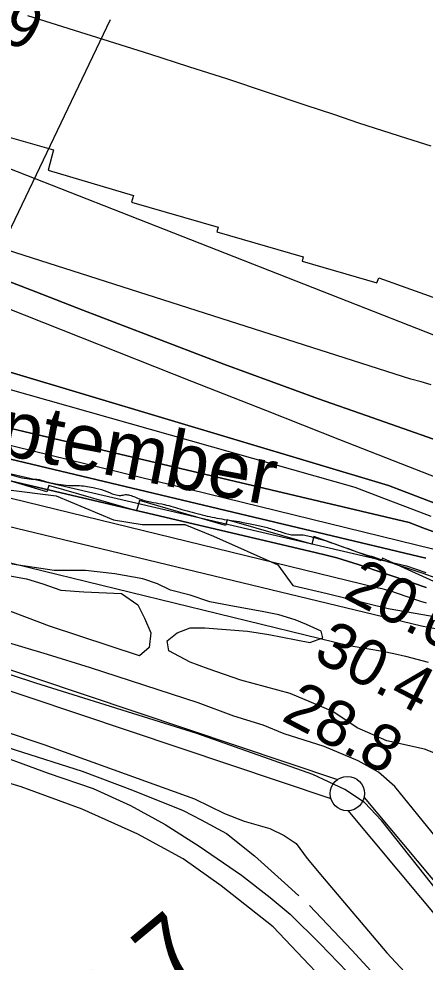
# Model space of a CAD drawing. Extents: x 3297772 to 3335630, y 634068 to 659439.
# Drawn here: x 3319783 to 3320374, y 645551 to 646925 of the extents above; entities that cross this region are included whole.
import ezdxf

# ---------------------------------------------------------------- set-up
doc = ezdxf.new("R2010")
doc.units = 0
for name, color, linetype in [('V-FLOD-BASE', 7, 'Continuous'), ('V-LEVE-TOET', 7, 'Continuous'), ('V-RIVR-EDGE', 7, 'Continuous'), ('V-RIVR-IDEN', 7, 'Continuous'), ('V-RIVR-RANG', 7, 'Continuous'), ('V-ROAD-CNTR', 7, 'Continuous'), ('V-RRAP-RVMT', 7, 'Continuous'), ('V-SITE-VEGE', 7, 'Continuous'), ('V-SURV-IDEN', 7, 'Continuous'), ('V-SURV-LINE', 7, 'Continuous'), ('V-TOPO-DPTH', 7, 'Continuous'), ('V-TOPO-MAJR', 7, 'Continuous'), ('V-TOPO-MINR', 7, 'Continuous'), ('V-TOPO-SHOR', 7, 'Continuous'), ('V-TOPO-WATR', 7, 'Continuous')]:
    doc.layers.add(name, color=color, linetype=linetype)

msp = doc.modelspace()

# ---------------------------------------------------------------- linework, layer by layer
at = {"layer": 'V-FLOD-BASE'}
msp.add_lwpolyline([(3320403.7, 645639.9), (3320311.2, 645756.9), (3320285.7, 645783.6), (3320257.2, 645802.4), (3320210.4, 645824.2), (3320041.7, 645883.8), (3319807.3, 645957.2), (3319603.1, 646024.5), (3319388.4, 646097.2), (3319091.5, 646194.7), (3318836.5, 646282.1)], dxfattribs=at)
at = {"layer": 'V-LEVE-TOET'}
for points in [[(3320390.6, 645731.9), (3320330, 645806.6), (3320306.1, 645827.7), (3320276.8, 645844.1), (3320226.9, 645865.1), (3320169.1, 645883.6), (3320138.2, 645896.1), (3320095.4, 645909.2), (3320043.9, 645928.6), (3319887.2, 645979.6), (3319824.6, 645998.9), (3319721.7, 646029.8), (3319592.6, 646079.4), (3319460.4, 646121.2), (3319353.4, 646159.9), (3319234.7, 646194.6), (3319013.7, 646271.3), (3318918.7, 646303.8)], [(3318948.8, 646161.3), (3319040.6, 646128), (3319139.6, 646094.7), (3319302.7, 646039.8), (3319440.5, 645992.5), (3319640.9, 645927.6), (3319819, 645868), (3320038.4, 645789), (3320082, 645767.2), (3320110.5, 645756.3), (3320147.8, 645745.5), (3320169.1, 645735.4), (3320186.6, 645723.7), (3320202.6, 645701.7), (3320224.9, 645675), (3320318.1, 645564.2), (3320410.4, 645465.3), (3320451, 645424.5), (3320501.1, 645383)]]:
    msp.add_lwpolyline(points, dxfattribs=at)
at = {"layer": 'V-RIVR-EDGE'}
msp.add_spline([(3314762, 649274.1), (3314790.4, 649247.4), (3314813.8, 649224.7), (3314842.2, 649196.8), (3314862.2, 649176.3), (3314886.7, 649152.1), (3314900.2, 649138.2), (3314917.7, 649122.8), (3314932.6, 649107.7), (3314956.3, 649080.3), (3314980, 649058.3), (3315004.5, 649036.7), (3315016.5, 649023.5), (3315034, 649001.5), (3315053.7, 648981.3), (3315075.9, 648956.4), (3315089, 648943.6), (3315090.5, 648939.2), (3315095.2, 648931.5), (3315116, 648911.7), (3315165.6, 648868.8), (3315188.6, 648851.6), (3315212.7, 648837.3), (3315236.1, 648818.9), (3315259, 648798.8), (3315272.2, 648788.2), (3315289, 648777.9), (3315298.5, 648775.3), (3315308.3, 648771.2), (3315320.4, 648764.6), (3315332, 648756.2), (3315345.5, 648749.2), (3315366, 648738.6), (3315396.3, 648721.7), (3315420, 648711), (3315449.6, 648697.4), (3315476.3, 648687.1), (3315490.9, 648684.9), (3315496.7, 648684.1), (3315504, 648679.4), (3315514.6, 648672), (3315516.8, 648666.9), (3315520.8, 648653.4), (3315527, 648639.8), (3315536.8, 648627), (3315543, 648621.5), (3315546.6, 648621.1), (3315552.5, 648618.6), (3315560.1, 648612.7), (3315568.5, 648604.6), (3315578, 648595.8), (3315593, 648584.8), (3315611.6, 648575.7), (3315624.4, 648570.1), (3315635, 648566.8), (3315640.8, 648563.5), (3315648.5, 648562.4), (3315656.2, 648563.1), (3315662.4, 648563.8), (3315671.1, 648560.9), (3315676.3, 648556.1), (3315679.2, 648552.8), (3315684.3, 648552.1), (3315687.9, 648551), (3315695.9, 648534.9), (3315725.4, 648474.9), (3315731.9, 648461.3), (3315736.7, 648455.8), (3315746.5, 648446.7), (3315756.7, 648438.2), (3315765.5, 648425.8), (3315772.8, 648408.9), (3315789.5, 648388.1), (3315803.7, 648364.6), (3315814.3, 648346.7), (3315830, 648328.4), (3315850.7, 648307.5), (3315869.7, 648285.5), (3315901.8, 648253.6), (3315937.5, 648219.5), (3315960.5, 648195.4), (3315980.9, 648175.6), (3315989.3, 648173.4), (3316000.6, 648165.3), (3316008.7, 648158.3), (3316031.6, 648140.7), (3316054.6, 648124.2), (3316085.3, 648105.5), (3316118.5, 648083.1), (3316140, 648068.8), (3316157.2, 648061.8), (3316170.3, 648056.7), (3316187.1, 648044.9), (3316195.5, 648041.2), (3316205.4, 648037.9), (3316215.2, 648033.2), (3316238.6, 648020.7), (3316243.7, 648016.6), (3316255, 648007.5), (3316268.9, 648000.1), (3316287.9, 647988.4), (3316303.6, 647982.9), (3316316.7, 647978.4), (3316339.4, 647970), (3316356.2, 647962.3), (3316375.5, 647951.2), (3316396.3, 647938), (3316428.4, 647920.4), (3316474.1, 647891.4), (3316489.4, 647882.2), (3316507.7, 647873.4), (3316517.5, 647867.9), (3316538, 647856.9), (3316563.5, 647842.9), (3316578.8, 647832.3), (3316609.5, 647815), (3316632.9, 647802.2), (3316646.7, 647790.8), (3316669.3, 647772.5), (3316682.1, 647762.2), (3316696.3, 647755.2), (3316758.8, 647713.8), (3316797.8, 647691), (3316819.7, 647676.7), (3316836.9, 647665.7), (3316865, 647650.6), (3316895.6, 647634.1), (3316912.4, 647623.1), (3316940.9, 647606.6), (3316996.7, 647574.7), (3317044.6, 647546.8), (3317079.2, 647525.1), (3317111.4, 647506.4), (3317148.2, 647484.7), (3317188.4, 647460.9), (3317213.9, 647442.2), (3317231.4, 647430.4), (3317255.2, 647416.8), (3317274.1, 647402.2), (3317293.1, 647391.1), (3317310.3, 647384.5), (3317333.7, 647373.5), (3317372.7, 647350.4), (3317404.1, 647330.9), (3317491, 647282.8), (3317527.8, 647261.5), (3317547.2, 647249.8), (3317572.4, 647235.8), (3317600.9, 647222.6), (3317629, 647207.9), (3317656.7, 647189.9), (3317738.1, 647140.4), (3317755.3, 647133.4), (3317770.2, 647129.3), (3317784.9, 647122.7), (3317817, 647104.7), (3317840.7, 647094.8), (3317860.1, 647086.3), (3317887.4, 647070.9), (3317915.2, 647055.5), (3317952.1, 647039.7), (3317972.9, 647031.6), (3318008.3, 647014.3), (3318036.8, 647000.4), (3318074.4, 646981.6), (3318112.3, 646961.1), (3318142.6, 646943.4), (3318179.2, 646929.1), (3318205.1, 646919.9), (3318226.3, 646909.6), (3318257.7, 646892.3), (3318275.6, 646883.5), (3318288.3, 646879.5), (3318295.7, 646878.7), (3318317.2, 646868.8), (3318334.3, 646857.1), (3318347.8, 646845.7), (3318357.3, 646839.5), (3318416.5, 646806.4), (3318459.2, 646781.4), (3318477.1, 646771.9), (3318503, 646757.2), (3318530, 646743.3), (3318562.1, 646728.6), (3318605.9, 646708.7), (3318643.9, 646694.4), (3318672.8, 646684.1), (3318690, 646679.6), (3318709, 646676.3), (3318727.2, 646668.6), (3318755, 646656.8), (3318823.6, 646624.5), (3318845.9, 646613.1), (3318855.7, 646607.9), (3318871.1, 646596.6), (3318891.9, 646586.3), (3318910.5, 646578.6), (3318938.6, 646566.8), (3318967.1, 646557.6), (3318997.8, 646547.6), (3319022.3, 646539.2), (3319054.4, 646528.1), (3319074.8, 646519.7), (3319089.5, 646516.3), (3319112.5, 646508.2), (3319131.8, 646500.1), (3319166.9, 646486.5), (3319188.4, 646478.8), (3319196.5, 646478.4), (3319208.5, 646474.7), (3319216.2, 646471.4), (3319227.9, 646467), (3319244, 646462.2), (3319256.7, 646456.3), (3319262.2, 646449.7), (3319272.4, 646444.6), (3319289.2, 646438.3), (3319307.1, 646430.3), (3319322.1, 646420.7), (3319337.4, 646409), (3319358.2, 646395), (3319379, 646382.6), (3319389.6, 646380), (3319400.6, 646376.3), (3319407.5, 646370.4), (3319419.9, 646362.7), (3319436.3, 646355), (3319463.4, 646344), (3319503.5, 646327.8), (3319544.4, 646316.7), (3319579.5, 646307.1), (3319606.2, 646299.4), (3319635, 646290.9), (3319681.4, 646280.9), (3319730.8, 646269.5), (3319772.8, 646260.6), (3319801.3, 646254.7), (3319808.9, 646254.6), (3319821.7, 646251.3), (3319836.3, 646248), (3319851, 646245.8), (3319868.1, 646245.4), (3319890.8, 646242.4), (3319906.9, 646238), (3319922.2, 646232.1), (3319931, 646230.9), (3319937.9, 646232), (3319943.8, 646231.3), (3319960.6, 646225), (3319978.8, 646220.6), (3319994.5, 646217.6), (3320020.1, 646210.6), (3320049.7, 646202.5), (3320078.2, 646196.6), (3320106.7, 646192.1), (3320126.8, 646188.1), (3320144.3, 646184), (3320163, 646178.1), (3320179.8, 646173.7), (3320196.6, 646173.3), (3320205.4, 646171.4), (3320223.3, 646166.6), (3320274.8, 646148.9), (3320298.9, 646141.2), (3320341.6, 646127.2), (3320376.3, 646115.8), (3320397.5, 646108.1), (3320422.7, 646098.5), (3320445, 646088.6), (3320487.3, 646068.4), (3320514, 646053.7), (3320559.9, 646025.8), (3320596.1, 646001.2), (3320629.6, 645979.6), (3320649.7, 645963.8), (3320673.1, 645949.8), (3320682.9, 645941.8), (3320711, 645921.2)], degree=3, dxfattribs=at)
at = {"layer": 'V-RIVR-RANG'}
msp.add_line((3319501, 646055.2), (3319915.9, 646924.2), dxfattribs=at)
at = {"layer": 'V-ROAD-CNTR'}
msp.add_lwpolyline([(3318578.7, 646244.3), (3319054.6, 646087.2), (3319608, 645901.5), (3319727.4, 645862), (3319825.5, 645826.2), (3319890.7, 645803.9), (3319945.4, 645779), (3319995.6, 645751.5), (3320045.1, 645719.9), (3320106.8, 645677.4), (3320148.4, 645645.1), (3320177.6, 645620.6), (3320221.5, 645577.6), (3320273.5, 645523.2), (3320384.6, 645404.9)], dxfattribs=at)
at = {"layer": 'V-RRAP-RVMT'}
for p, q in [((3319700.6, 646772.5), (3319833.3, 646734.3)), ((3319833.3, 646734.3), (3319825.3, 646704.6)), ((3319825.3, 646704.6), (3319949.6, 646668)), ((3319949.6, 646668), (3319946.8, 646658.4)), ((3319946.8, 646658.4), (3320072.7, 646621.8)), ((3320072.7, 646621.8), (3320071.1, 646615.1)), ((3320071.1, 646615.1), (3320196.6, 646578.4)), ((3320196.6, 646578.4), (3320195, 646572.2)), ((3320195, 646572.2), (3320303.8, 646540.6)), ((3320303.8, 646540.6), (3320306.6, 646548.1)), ((3320306.6, 646548.1), (3320425.4, 646505)), ((3319823.6, 646236.1), (3319702, 646272)), ((3319826.3, 646245.4), (3319823.6, 646236.1)), ((3319954.1, 646208.3), (3319826.3, 646245.4)), ((3319958.5, 646223.4), (3319954.1, 646208.3)), ((3320083.6, 646186.9), (3319958.5, 646223.4)), ((3320086, 646195.4), (3320083.6, 646186.9)), ((3320209, 646159.8), (3320086, 646195.4)), ((3320212.3, 646170.9), (3320209, 646159.8)), ((3320310.3, 646135.4), (3320212.3, 646170.9)), ((3320311.8, 646139.4), (3320310.3, 646135.4)), ((3320397.4, 646100.8), (3320311.8, 646139.4))]:
    msp.add_line(p, q, dxfattribs=at)
at = {"layer": 'V-SITE-VEGE'}
for points in [[(3318745.1, 646603.2), (3319169.8, 646459.4), (3319283.5, 646425.9), (3319340.4, 646397.5), (3319377.1, 646379.1), (3319410.6, 646344), (3319457.4, 646308.8), (3319489.2, 646287.1), (3319504.4, 646283.8), (3319589.5, 646265.3), (3319689.8, 646248.6), (3319837, 646230.2), (3319920.6, 646195.1), (3319962.4, 646188.4), (3320024.3, 646188.4), (3320066.1, 646171.7), (3320159.7, 646129.9), (3320181.4, 646099.7), (3320231.6, 646088), (3320320.2, 646066.3), (3320407.2, 646051.2)], [(3319753.2, 646116.6), (3319793.7, 646109.4), (3319817.6, 646102.3), (3319843.8, 646092.7), (3319877.2, 646090.4), (3319932, 646088), (3319955.8, 646071.3), (3319965.4, 646052.2), (3319974.9, 646030.7), (3319972.5, 646009.3), (3319958.2, 645997.3), (3319827.1, 646040.3), (3319543.4, 646147.6)], [(3320408.8, 645847.1), (3320373, 645861.4), (3320318.2, 645873.3), (3320275.3, 645892.4), (3320239.5, 645916.2), (3320177.6, 645942.5), (3320106, 645961.6), (3320058.4, 645978.2), (3320032.1, 645987.8), (3320001.1, 646004.5), (3319998.8, 646018.8), (3320013.1, 646030.7), (3320032.1, 646037.9), (3320053.6, 646037.9), (3320084.6, 646035.5), (3320115.6, 646033.1), (3320146.6, 646028.3), (3320206.2, 646016.4), (3320225.2, 646023.6), (3320222.9, 646033.1), (3320201.4, 646042.6), (3320184.7, 646049.8), (3320160.9, 646057), (3320137, 646061.7), (3320096.5, 646068.9), (3320060.7, 646076), (3320032.1, 646085.6), (3320003.5, 646092.7), (3319984.5, 646102.3), (3319963, 646109.4), (3319922.5, 646116.6), (3319879.6, 646121.4), (3319834.3, 646121.4), (3319772.3, 646130.9)]]:
    msp.add_lwpolyline(points, dxfattribs=at)
at = {"layer": 'V-SURV-LINE'}
for points in [[(3318337.4, 646458.2), (3320246.7, 645817.1)], [(3320237.2, 645788.7), (3318327.9, 646429.7)], [(3320285.2, 645790.8), (3320496.8, 645537.7)], [(3320473.8, 645518.4), (3320262.2, 645771.6)]]:
    msp.add_lwpolyline(points, dxfattribs=at)
msp.add_circle((3320260.9, 645796.5), 25, dxfattribs=at)
at = {"layer": 'V-TOPO-DPTH'}
for points in [[(3318953.3, 646768.9), (3318982.8, 646757.8), (3319084.4, 646720.7), (3319544.5, 646588.3), (3319550.2, 646586.8), (3319555.9, 646585.2), (3319558.5, 646584.4), (3319562.9, 646583.1), (3319567.3, 646581.7), (3319571.6, 646580.3), (3319576, 646578.7), (3319581.3, 646576.8), (3319584.6, 646575.6), (3319587.9, 646574.3), (3319818.8, 646482.8), (3319926.4, 646440.1), (3320034.1, 646397.5), (3320141.9, 646355), (3320249.6, 646312.5), (3320459, 646230.1)], [(3318953.3, 646768.9), (3318982.8, 646757.8), (3319084.4, 646720.7), (3319544.5, 646588.3), (3319550.2, 646586.8), (3319555.9, 646585.2), (3319558.5, 646584.4), (3319562.9, 646583.1), (3319567.3, 646581.7), (3319571.6, 646580.3), (3319576, 646578.7), (3319581.3, 646576.8), (3319584.6, 646575.6), (3319587.9, 646574.3), (3319818.8, 646482.8), (3319926.4, 646440.1), (3320034.1, 646397.5), (3320141.9, 646355), (3320249.6, 646312.5), (3320459, 646230.1)], [(3318911.1, 646723.6), (3318963.9, 646700.4), (3318999.6, 646685.1), (3319035.5, 646670.1), (3319071.6, 646655.7), (3319107.8, 646641.6), (3319530.6, 646481.1), (3319535.1, 646479.6), (3319537.3, 646479), (3319539.6, 646478.4), (3319546.2, 646477), (3319549.5, 646476.5), (3320320.6, 646245.3), (3320409.6, 646211.2)], [(3320409.6, 646211.2), (3320320.6, 646245.3), (3319549.5, 646476.5), (3319546.2, 646477), (3319539.6, 646478.4), (3319537.3, 646479), (3319535.1, 646479.6), (3319530.6, 646481.1), (3319107.8, 646641.6), (3319071.6, 646655.7), (3319035.5, 646670.1), (3318999.6, 646685.1), (3318963.9, 646700.4), (3318911.1, 646723.6)], [(3320390.7, 646176.2), (3320370.8, 646183.7), (3320350.8, 646191.3), (3319491.6, 646394.6), (3319489.7, 646395.4), (3318915.6, 646662.3)], [(3318915.6, 646662.3), (3319489.7, 646395.4), (3319491.6, 646394.6), (3320350.8, 646191.3), (3320370.8, 646183.7), (3320390.7, 646176.2)], [(3320375, 646139.7), (3319509.6, 646345.7), (3319491.6, 646353.1), (3319473.7, 646360.6), (3319455.8, 646368.3), (3319438.1, 646376.1), (3319090.2, 646532.4), (3319048.1, 646551.3), (3319006.1, 646570.3), (3318964.1, 646589.4), (3318922.1, 646608.5)], [(3318922.1, 646608.5), (3318964.1, 646589.4), (3319006.1, 646570.3), (3319048.1, 646551.3), (3319090.2, 646532.4), (3319438.1, 646376.1), (3319455.8, 646368.3), (3319473.7, 646360.6), (3319491.6, 646353.1), (3319509.6, 646345.7), (3320375, 646139.7)], [(3320375.4, 646096.6), (3320357.1, 646102.9), (3320276.7, 646130.3), (3320261.2, 646135.2), (3320245.6, 646139.9), (3320229.9, 646144), (3320214.1, 646147.7), (3319455.7, 646325.9), (3319419.8, 646341.2), (3319384, 646356.9), (3319375.5, 646360.6), (3319335.5, 646378.3), (3319295.5, 646396), (3319255.4, 646413.6), (3319215.4, 646431.3), (3318874.5, 646581.2)], [(3320440, 646293.9), (3320288.2, 646347.2), (3320219.1, 646371.8), (3320150.1, 646396.8), (3320081.3, 646422.3), (3320012.7, 646448.2), (3319944.2, 646474.5), (3319875.7, 646500.8), (3319807.2, 646527.3), (3319738.8, 646553.8)], [(3320440, 646293.9), (3320288.2, 646347.2), (3320219.1, 646371.8), (3320150.1, 646396.8), (3320081.3, 646422.3), (3320012.7, 646448.2), (3319944.2, 646474.5), (3319875.7, 646500.8), (3319807.2, 646527.3), (3319738.8, 646553.8)]]:
    msp.add_lwpolyline(points, dxfattribs=at)
at = {"layer": 'V-TOPO-MAJR'}
for points in [[(3320382.8, 646392.2), (3320368.2, 646396.4), (3320353.5, 646400.3), (3319717.1, 646603.9), (3319694, 646612.7), (3319670.9, 646621.5), (3319667.8, 646622.7), (3319643.2, 646632), (3319618.5, 646641.2), (3319593.7, 646650.2), (3319568.9, 646659.1), (3319390.7, 646722.2), (3319322.7, 646746.6), (3319255, 646771.6), (3319187.6, 646797.3), (3319120.3, 646823.5), (3319030.2, 646859.2), (3319008.2, 646868.1), (3318986.3, 646877.4), (3318964.6, 646887), (3318943.1, 646896.9)], [(3318806.3, 646493.5), (3319310, 646266.1), (3319325.6, 646259.2), (3319341.3, 646252.3), (3319357, 646245.6), (3319372.7, 646239), (3319388.6, 646232.6), (3319404.4, 646226.3), (3319420.3, 646220.2), (3319436.3, 646214.1), (3320263, 646012.2), (3320266.4, 646011.9), (3320311.8, 646003.9), (3320328.7, 646000.6), (3320345.5, 645996.9), (3320362.1, 645992.5), (3320378.7, 645987.8)]]:
    msp.add_lwpolyline(points, dxfattribs=at)
at = {"layer": 'V-TOPO-MINR'}
for points in [[(3320539.9, 646404.4), (3319678.9, 646742.4), (3319675, 646742.8), (3319671, 646743.4), (3319124.8, 646860.5), (3319104.5, 646867.2), (3319084.5, 646874.3), (3319064.7, 646882.2), (3319045.1, 646890.6), (3319015.5, 646903.9), (3319010.9, 646906), (3319006.3, 646908.2), (3318254.2, 647265.3)], [(3319795.5, 646930.3), (3319973.1, 646874.1), (3320029.8, 646856), (3320086.4, 646837.7), (3320142.8, 646819), (3320199.2, 646800.1), (3320242.1, 646785.7), (3320277.1, 646774), (3320312.1, 646762.5), (3320347.2, 646751.3), (3320382.4, 646740.3)], [(3318953.3, 646768.9), (3318982.8, 646757.8), (3319084.4, 646720.7), (3319544.5, 646588.3), (3319550.2, 646586.8), (3319555.9, 646585.2), (3319558.5, 646584.4), (3319562.9, 646583.1), (3319567.3, 646581.7), (3319571.6, 646580.3), (3319576, 646578.7), (3319581.3, 646576.8), (3319584.6, 646575.6), (3319587.9, 646574.3), (3319818.8, 646482.8), (3319926.4, 646440.1), (3320034.1, 646397.5), (3320141.9, 646355), (3320249.6, 646312.5), (3320459, 646230.1)], [(3318911.1, 646723.6), (3318963.9, 646700.4), (3318999.6, 646685.1), (3319035.5, 646670.1), (3319071.6, 646655.7), (3319107.8, 646641.6), (3319530.6, 646481.1), (3319535.1, 646479.6), (3319537.3, 646479), (3319539.6, 646478.4), (3319546.2, 646477), (3319549.5, 646476.5), (3320320.6, 646245.3), (3320409.6, 646211.2)], [(3318920.9, 646689.8), (3319101, 646608.9), (3319169.4, 646579), (3319238.1, 646550.2), (3319307.5, 646522.9), (3319377.3, 646496.5), (3320271.7, 646243), (3320313.7, 646226.9), (3320355.7, 646210.9), (3320382.4, 646200.8)], [(3318854.8, 646661.4), (3319464.8, 646385.5), (3319473.6, 646381.5), (3319482.5, 646377.7), (3319491.4, 646373.9), (3319500.4, 646370.3), (3320411.2, 646146.8)], [(3318915.6, 646662.3), (3319489.7, 646395.4), (3319491.6, 646394.6), (3320350.8, 646191.3), (3320370.8, 646183.7), (3320390.7, 646176.2)], [(3318865.5, 646610.5), (3318997.8, 646551.2), (3319075.6, 646516.4), (3319153.3, 646481.6), (3319231.1, 646446.9), (3319308.9, 646412.2), (3319411.1, 646366.6), (3319437.9, 646354.8), (3319464.7, 646343.3), (3319491.7, 646332.1), (3319518.8, 646321.1), (3320347, 646128.3), (3320375.2, 646118.6)], [(3318815.9, 646580.4), (3319426.3, 646316.2), (3319429.7, 646314.8), (3319433, 646313.3), (3319436.3, 646311.9), (3319439.7, 646310.4), (3319443, 646309), (3319446.3, 646307.5), (3319449.7, 646306.1), (3319453.1, 646304.8), (3320303.8, 646096.9), (3320310.9, 646095.2), (3320317.9, 646093.4), (3320324.9, 646091.3), (3320331.9, 646089.1), (3320367.5, 646077), (3320375.7, 646074.2)], [(3318874.5, 646581.2), (3319215.4, 646431.3), (3319255.4, 646413.6), (3319295.5, 646396), (3319335.5, 646378.3), (3319375.5, 646360.6), (3319384, 646356.9), (3319419.8, 646341.2), (3319455.7, 646325.9), (3320214.1, 646147.7), (3320229.9, 646144), (3320245.6, 646139.9), (3320261.2, 646135.2), (3320276.7, 646130.3), (3320357.1, 646102.9), (3320375.4, 646096.6)], [(3319738.8, 646553.8), (3319807.2, 646527.3), (3319875.7, 646500.8), (3319944.2, 646474.5), (3320012.7, 646448.2), (3320081.3, 646422.3), (3320150.1, 646396.8), (3320219.1, 646371.8), (3320288.2, 646347.2), (3320440, 646293.9)], [(3318949.4, 646477.7), (3319006.9, 646453.1), (3319064.4, 646428.5), (3319122, 646403.9), (3319394.7, 646287.6), (3319411.7, 646280.4), (3319428.7, 646273.3), (3319445.7, 646266.2), (3319462.7, 646259.3), (3320368.6, 646041.1), (3320389.3, 646036.8)]]:
    msp.add_lwpolyline(points, dxfattribs=at)
at = {"layer": 'V-TOPO-SHOR'}
for points in [[(3318258.7, 646377.3), (3318311.9, 646354.7), (3318366.7, 646333.7), (3318447, 646305.7), (3318575.6, 646263.9), (3318736.9, 646209.5), (3318875.9, 646162.2), (3319068.1, 646097.8), (3319203.9, 646053.6), (3319346.8, 646007), (3319562.9, 645932.5), (3319727.3, 645877.4), (3319777.3, 645860.3), (3319875, 645829.3), (3319948.1, 645801.3), (3320022, 645771.7), (3320048.2, 645758.4), (3320084.8, 645738.1), (3320125.5, 645705.9), (3320169.3, 645666.6), (3320190, 645647.7)], [(3320343.5, 645400), (3320266.9, 645481.9), (3320152.7, 645602.3), (3320077, 645662), (3320022.1, 645701.2), (3319956.1, 645737.2), (3319875, 645773.8), (3319786, 645806.5), (3319703.4, 645831.3), (3319690, 645830.4), (3319686.1, 645825.6), (3319669.7, 645790.6), (3319563.4, 645574.3), (3319458, 645358.1), (3319360.4, 645152.2), (3319254.9, 644936.7), (3319214.3, 644850.8)], [(3320206, 645633.6), (3320267.5, 645568.2), (3320388, 645436.8), (3320433.5, 645392.7), (3320459.8, 645370.7), (3320493.3, 645345.6), (3320526.7, 645324.4), (3320553.7, 645312.7), (3320631.6, 645281.6), (3320748.4, 645240.4), (3320928.7, 645177.5), (3321089.9, 645119.2), (3321203.5, 645078), (3321353.7, 645023.6), (3321408.5, 645001), (3321517.3, 644966.9), (3321587.2, 644946), (3321636.4, 644933.7), (3321671.3, 644925.2), (3321737.2, 644913), (3321841, 644903.5), (3321926.7, 644888.2), (3322063.9, 644870.2), (3322259.1, 644841.4)]]:
    msp.add_lwpolyline(points, dxfattribs=at)
at = {"layer": 'V-TOPO-WATR'}
msp.add_lwpolyline([(3318922.1, 646608.5), (3318964.1, 646589.4), (3319006.1, 646570.3), (3319048.1, 646551.3), (3319090.2, 646532.4), (3319438.1, 646376.1), (3319455.8, 646368.3), (3319473.7, 646360.6), (3319491.6, 646353.1), (3319509.6, 646345.7), (3320375, 646139.7)], dxfattribs=at)

# ---------------------------------------------------------------- texts
at = {"layer": 'V-RIVR-IDEN'}
msp.add_text('September', height=83, rotation=349.2687, dxfattribs=at).set_placement((3319616.1, 646316.9))
at = {"layer": 'V-RIVR-RANG'}
for s, rotation, p in [('-59', 332.6861, (3319679.7, 646935)), ('20.0', 332.3983, (3320252.7, 646082.7)), ('30.4', 332.3983, (3320209.1, 645992.6)), ('28.8', 332.3983, (3320163, 645903.9))]:
    msp.add_text(s, height=67, rotation=rotation, dxfattribs=at).set_placement(p)
at = {"layer": 'V-SURV-IDEN'}
msp.add_text('4596+91.7', height=100, rotation=39.8256, dxfattribs=at).set_placement((3319572.5, 645145.8))

doc.saveas('drawing.dxf')
